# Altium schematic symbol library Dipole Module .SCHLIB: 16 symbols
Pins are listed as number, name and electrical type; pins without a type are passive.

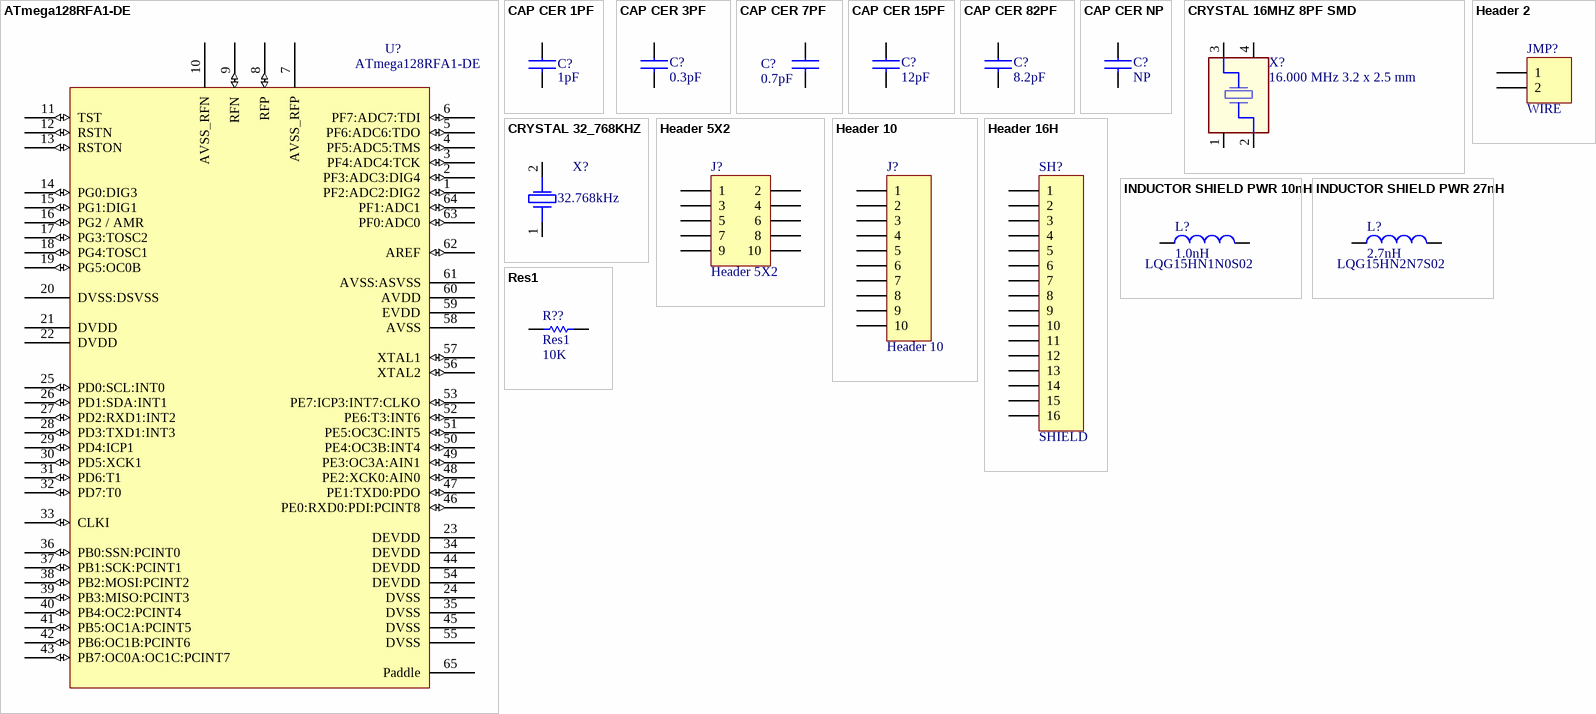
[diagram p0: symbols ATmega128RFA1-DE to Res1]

## ATmega128RFA1-DE
designator U?
802.15.4 compliant AVR transceiver
footprint MLF64-M2
pins: 1 PF2:ADC2:DIG2 (io), 2 PF3:ADC3:DIG4 (io), 3 PF4:ADC4:TCK (io), 4 PF5:ADC5:TMS (io), 5 PF6:ADC6:TDO (io), 6 PF7:ADC7:TDI (io), 7 AVSS_RFP (power), 8 RFP (io), 9 RFN (io), 10 AVSS_RFN (power), 11 TST (io), 12 RSTN (io), 13 RSTON (io), 14 PG0:DIG3 (io), 15 PG1:DIG1 (io), 16 PG2 / AMR (io), 17 PG3:TOSC2 (io), 18 PG4:TOSC1 (io), 19 PG5:OC0B (io), 20 DVSS:DSVSS (power), 21 DVDD (power), 22 DVDD (power), 23 DEVDD (power), 24 DVSS (power), 25 PD0:SCL:INT0 (io), 26 PD1:SDA:INT1 (io), 27 PD2:RXD1:INT2 (io), 28 PD3:TXD1:INT3 (io), 29 PD4:ICP1 (io), 30 PD5:XCK1 (io), 31 PD6:T1 (io), 32 PD7:T0 (io), 33 CLKI (io), 34 DEVDD (power), 35 DVSS (power), 36 PB0:SSN:PCINT0 (io), 37 PB1:SCK:PCINT1 (io), 38 PB2:MOSI:PCINT2 (io), 39 PB3:MISO:PCINT3 (io), 40 PB4:OC2:PCINT4 (io), 41 PB5:OC1A:PCINT5 (io), 42 PB6:OC1B:PCINT6 (io), 43 PB7:OC0A:OC1C:PCINT7 (io), 44 DEVDD (power), 45 DVSS (power), 46 PE0:RXD0:PDI:PCINT8 (io), 47 PE1:TXD0:PDO (io), 48 PE2:XCK0:AIN0 (io), 49 PE3:OC3A:AIN1 (io), 50 PE4:OC3B:INT4 (io), 51 PE5:OC3C:INT5 (io), 52 PE6:T3:INT6 (io), 53 PE7:ICP3:INT7:CLKO (io), 54 DEVDD (power), 55 DVSS (power), 56 XTAL2 (io), 57 XTAL1 (io), 58 AVSS (power), 59 EVDD (power), 60 AVDD (power), 61 AVSS:ASVSS (power), 62 AREF (io), 63 PF0:ADC0 (io), 64 PF1:ADC1 (io), 65 Paddle (power)

## CAP CER 1PF
designator C?, comment 1pF
CAP CER 1PF
footprint 0402-POL
pins: 1, 2

## CAP CER 3PF
designator C?, comment 0.3pF
CAP CER 3PF
footprint 0402
pins: 1, 2

## CAP CER 7PF
designator C?, comment 0.7pF
CAP CER 7PF
footprint 0402
pins: 1, 2

## CAP CER 15PF
designator C?, comment 12pF
CAP CER 15PF
footprint 0603
pins: 1, 2

## CAP CER 82PF
designator C?, comment 8.2pF
CAP CER 82PF
footprint 0402
pins: 1, 2

## CAP CER NP
designator C?, comment NP
CAP CER NP
footprint 0402
pins: 1, 2

## CRYSTAL 16MHZ 8PF SMD
designator X?, comment 16.000 MHz 3.2 x 2.5 mm
CRYSTAL 16MHZ 8PF SMD; Manufacturer: Kyocera; Value: CX3225GB16000D0HPQZ1
footprint XTAL16MHZKYOCERA
pins: 1, 2, 3, 4

## CRYSTAL 32_768KHZ
designator X?, comment 32.768kHz
CRYSTAL 16MHZ 8PF SMD; Manufacturer: Abracon
footprint XTAL32_768KHZ_ABRACON
pins: 1, 2

## Header 2
designator JMP?, comment WIRE
Header, 2-Pin
footprint 2010_JUMPER
pins: 1, 2

## Header 5X2
designator J?
Header, 5-Pin, Dual row
pins: 1, 2, 3, 4, 5, 6, 7, 8, 9, 10

## Header 10
designator J?
Header, 10-Pin
footprint HDR1X10
pins: 1, 2, 3, 4, 5, 6, 7, 8, 9, 10

## Header 16H
designator SH?, comment SHIELD
Header, 16-Pin, Right Angle
footprint SHIELD_BMI-S-103_LAIRD
pins: 1, 2, 3, 4, 5, 6, 7, 8, 9, 10, 11, 12, 13, 14, 15, 16

## INDUCTOR SHIELD PWR 10nH
designator L?, comment LQG15HN1N0S02  value 1.0nH
1.0nH
footprint 0402-POL
pins: 1, 2

## INDUCTOR SHIELD PWR 27nH
designator L?, comment LQG15HN2N7S02  value 2.7nH
27nH
footprint 0402-POL
pins: 1, 2

## Res1
designator R??  value 10K
Resistor
footprint AXIAL-0.3 (Axial Device, Thru-Hole; 2 Leads; 0.3 in Pin Spacing)
simulation model RESISTOR (Resistor)
signal-integrity model Res
pins: 1, 2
